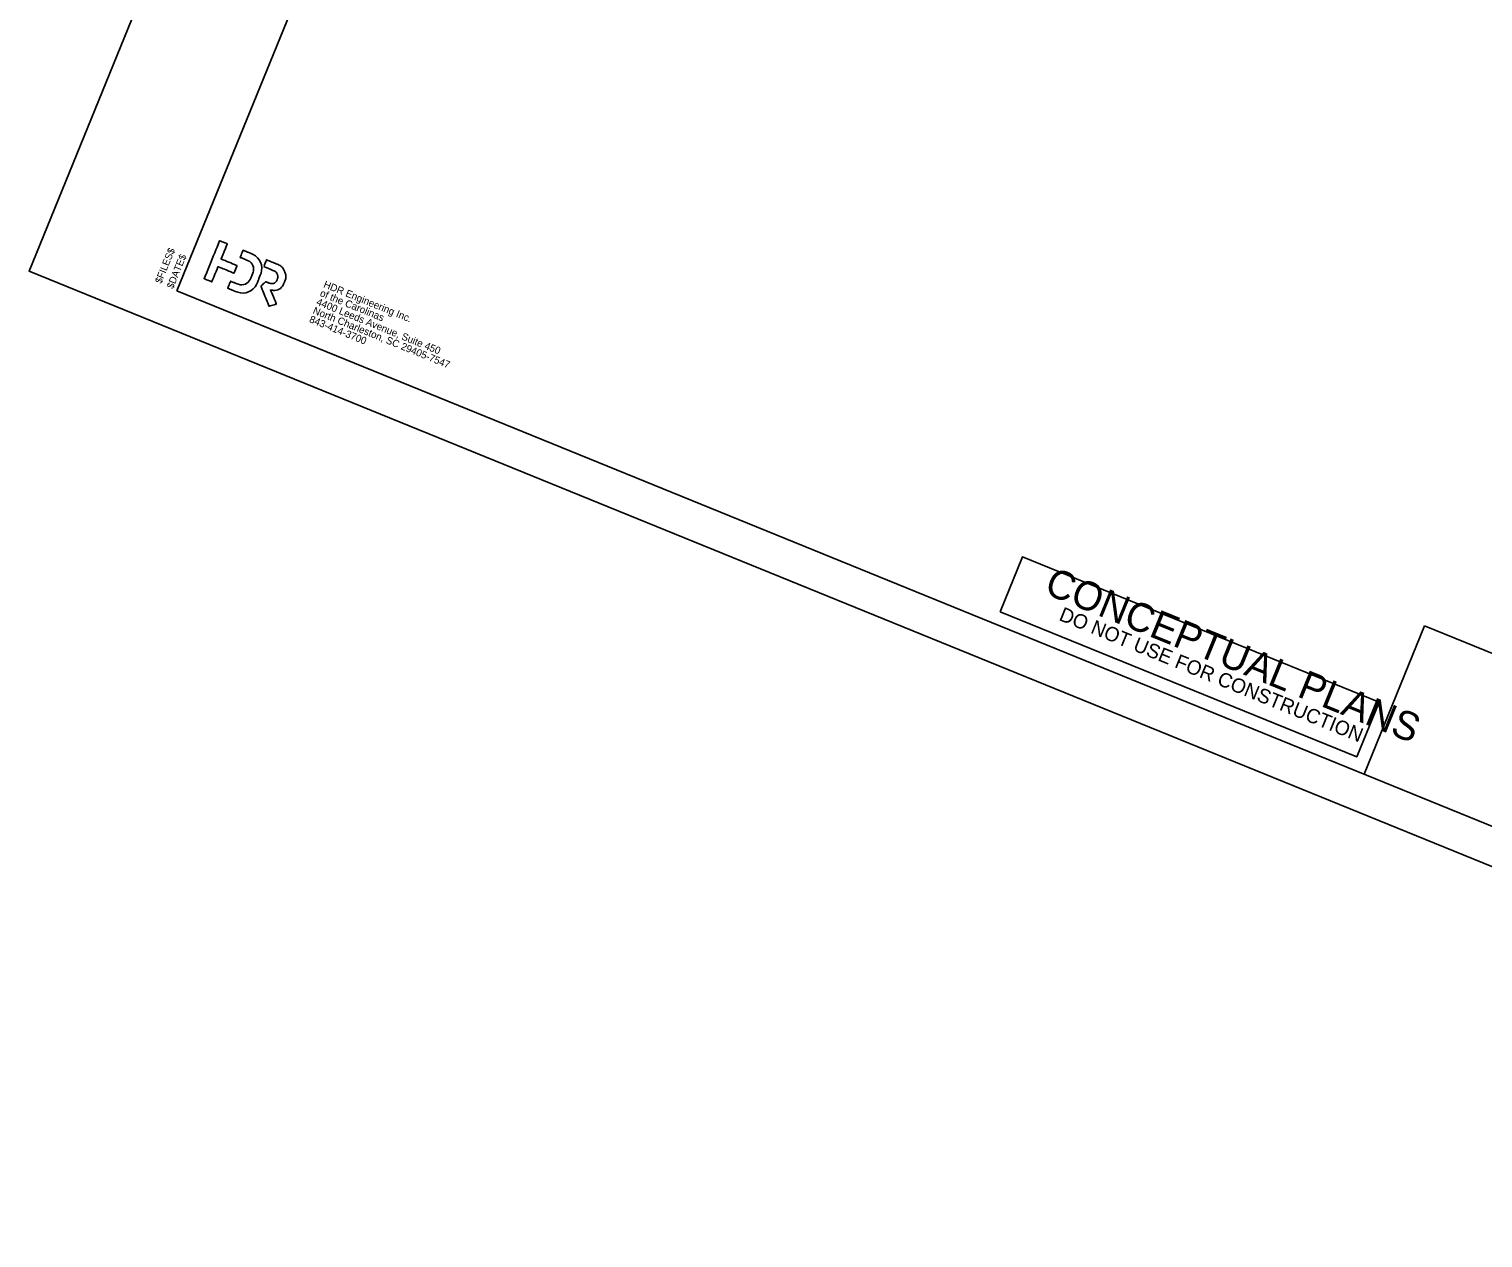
# Model space of a CAD drawing. Extents: x 2163359 to 2164192, y 212749 to 213428.
# Drawn here: x 2163359.4 to 2163767.6, y 212748.5 to 213088.1 of the extents above; entities that cross this region are included whole.
import ezdxf

# ---------------------------------------------------------------- set-up
doc = ezdxf.new("R2010")
doc.units = 0
for name, color, linetype in [('RD_SHT_Bndy', 7, 'Continuous'), ('RD_SHT_ID', 7, 'Continuous'), ('RD_SHT_IplotShp', 7, 'Continuous'), ('RD_SHT_Misc1', 7, 'Continuous'), ('RD_SHT_Misc4', 7, 'Continuous'), ('RD_SHT_Typical', 7, 'Continuous')]:
    doc.layers.add(name, color=color, linetype=linetype)

msp = doc.modelspace()

# ---------------------------------------------------------------- linework, layer by layer
at = {"layer": 'RD_SHT_Bndy'}
for p, q in [((2163559.35, 213403.51), (2163400.92, 213014.53)), ((2163400.92, 213014.53), (2164021.42, 212761.8))]:
    msp.add_line(p, q, dxfattribs=at)
at = {"layer": 'RD_SHT_ID'}
for points in [[(2163417.81, 213021.67), (2163417.81, 213021.67), (2163413.32, 213023.5), (2163413.32, 213023.5), (2163413.32, 213023.5), (2163413.32, 213023.5), (2163415.06, 213027.77), (2163415.06, 213027.77), (2163415.06, 213027.77), (2163415.06, 213027.77), (2163412.89, 213028.65), (2163412.89, 213028.65), (2163412.89, 213028.65), (2163412.89, 213028.65), (2163408.54, 213017.98), (2163408.54, 213017.98), (2163408.54, 213017.98), (2163408.54, 213017.98), (2163410.71, 213017.09), (2163410.71, 213017.09), (2163410.71, 213017.09), (2163410.71, 213017.09), (2163412.45, 213021.37), (2163412.45, 213021.37), (2163412.45, 213021.37), (2163412.45, 213021.37), (2163416.94, 213019.54), (2163416.94, 213019.54), (2163416.94, 213019.54), (2163416.94, 213019.54), (2163417.81, 213021.67), (2163417.81, 213021.67)], [(2163423.92, 213017.94), (2163423.92, 213017.94), (2163423.92, 213017.95), (2163423.92, 213017.95), (2163423.92, 213017.95), (2163423.92, 213017.95), (2163423.92, 213017.95), (2163423.92, 213017.95), (2163423.92, 213017.95), (2163425.17, 213021.04), (2163423.84, 213024.19), (2163420.75, 213025.45), (2163420.75, 213025.45), (2163420.75, 213025.45), (2163419.49, 213025.96), (2163419.49, 213025.96), (2163419.49, 213025.96), (2163419.49, 213025.96), (2163418.67, 213023.96), (2163418.67, 213023.96), (2163418.67, 213023.96), (2163418.67, 213023.96), (2163419.94, 213023.45), (2163419.94, 213023.45), (2163419.94, 213023.45), (2163421.9, 213022.65), (2163422.71, 213020.72), (2163421.92, 213018.76), (2163421.92, 213018.76), (2163421.11, 213016.8), (2163419.18, 213015.98), (2163417.22, 213016.78), (2163417.22, 213016.78), (2163417.22, 213016.78), (2163415.96, 213017.29), (2163415.96, 213017.29), (2163415.96, 213017.29), (2163415.96, 213017.29), (2163415.14, 213015.29), (2163415.14, 213015.29), (2163415.14, 213015.29), (2163415.14, 213015.29), (2163416.4, 213014.77), (2163416.4, 213014.77), (2163416.4, 213014.77), (2163419.49, 213013.51), (2163422.65, 213014.85), (2163423.92, 213017.94), (2163423.92, 213017.94), (2163423.92, 213017.94), (2163423.92, 213017.94), (2163423.92, 213017.94), (2163423.92, 213017.94), (2163423.92, 213017.94), (2163423.92, 213017.94), (2163423.92, 213017.94)], [(2163425.31, 213021.36), (2163425.31, 213021.36), (2163427.72, 213020.37), (2163427.72, 213020.37), (2163427.72, 213020.37), (2163428.45, 213020.08), (2163428.88, 213019.72), (2163429.09, 213019.23), (2163429.09, 213019.23), (2163429.28, 213018.78), (2163429.28, 213018.29), (2163429.09, 213017.82), (2163429.09, 213017.82), (2163428.65, 213016.74), (2163427.45, 213016.48), (2163426.42, 213016.9), (2163426.42, 213016.9), (2163426.42, 213016.9), (2163425.82, 213017.14), (2163425.82, 213017.14), (2163425.82, 213017.14), (2163425.82, 213017.14), (2163424.49, 213015.91), (2163424.49, 213015.91), (2163424.49, 213015.91), (2163424.49, 213015.91), (2163426.77, 213010.21), (2163426.77, 213010.21), (2163426.77, 213010.21), (2163426.77, 213010.21), (2163428.82, 213010.87), (2163428.82, 213010.87), (2163428.82, 213010.87), (2163428.82, 213010.87), (2163427.18, 213014.83), (2163427.18, 213014.83), (2163427.18, 213014.83), (2163428.84, 213014.49), (2163430.47, 213015.47), (2163431.07, 213016.96), (2163431.07, 213016.96), (2163431.53, 213018.07), (2163431.56, 213019.06), (2163431.07, 213020.13), (2163431.07, 213020.13), (2163430.56, 213021.24), (2163429.73, 213021.8), (2163428.35, 213022.36), (2163428.35, 213022.36), (2163428.35, 213022.36), (2163426.09, 213023.28), (2163426.09, 213023.28), (2163426.09, 213023.28), (2163426.09, 213023.28), (2163425.31, 213021.36), (2163425.31, 213021.36)]]:
    msp.add_open_spline(points, degree=3, dxfattribs=at)
at = {"layer": 'RD_SHT_IplotShp'}
msp.add_lwpolyline([(2163525.37, 213427.64), (2164192.18, 213156.04), (2164026.21, 212748.55), (2163359.39, 213020.14)], close=True, dxfattribs=at)
at = {"layer": 'RD_SHT_Misc4'}
for p, q in [((2163734.25, 212878.77), (2163751.22, 212920.44)), ((2163751.22, 212920.44), (2163834.57, 212886.49))]:
    msp.add_line(p, q, dxfattribs=at)
at = {"layer": 'RD_SHT_Typical'}
msp.add_lwpolyline([(2163632.03, 212924.45), (2163638.31, 212939.86), (2163738.47, 212899.06), (2163732.19, 212883.65)], close=True, dxfattribs=at)

# ---------------------------------------------------------------- texts
at = {"layer": 'RD_SHT_ID'}
for s, p in [('HDR Engineering Inc.', (2163441.87, 213015.62)), ('4400 Leeds Avenue, Suite 450', (2163439.88, 213010.73)), ('of the Carolinas', (2163440.88, 213013.17)), ('843-414-3700', (2163437.89, 213005.84)), ('North Charleston, SC 29405-7547', (2163438.89, 213008.28))]:
    msp.add_text(s, height=2.04, rotation=337.8388, dxfattribs=at).set_placement(p)
at = {"layer": 'RD_SHT_Misc1'}
for s, p in [('$FILES$', (2163396.5, 213016.45)), ('$DATE$', (2163399.81, 213014.98))]:
    msp.add_text(s, height=2, rotation=67.8388, dxfattribs=at).set_placement(p)
at = {"layer": 'RD_SHT_Typical'}
for s, height, p in [('CONCEPTUAL PLANS', 8.064, (2163644.09, 212929.68)), ('DO NOT USE FOR CONSTRUCTION', 4.032, (2163648.3, 212922.15))]:
    msp.add_text(s, height=height, rotation=337.8388, dxfattribs=at).set_placement(p)

doc.saveas('drawing.dxf')
